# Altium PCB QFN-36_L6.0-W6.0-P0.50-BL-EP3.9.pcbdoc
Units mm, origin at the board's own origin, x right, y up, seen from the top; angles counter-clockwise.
Board outline 19.5 x 19.8 mm, 2 copper layers (Top Layer, Bottom Layer), stack 0 mm thick; 1 components, 0 nets, 37 pads, 0 vias.
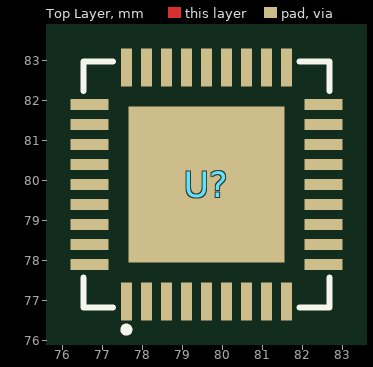
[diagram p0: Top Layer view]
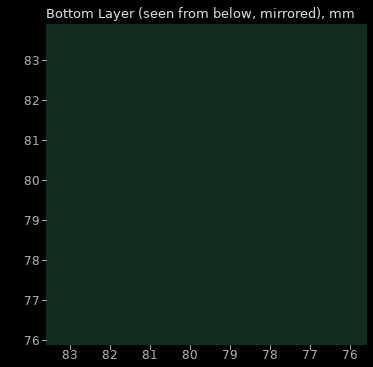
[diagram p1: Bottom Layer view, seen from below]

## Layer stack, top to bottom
Top Layer: signal copper (thickness not stored)
Bottom Layer: signal copper (thickness not stored)

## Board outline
89.35,69.85 69.85,69.85 69.85,89.655 89.35,89.655

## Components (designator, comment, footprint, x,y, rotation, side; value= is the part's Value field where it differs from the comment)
U? "" QFN-36_L6.0-W6.0-P0.50-BL-EP3.9 79.6,79.905 r0 top

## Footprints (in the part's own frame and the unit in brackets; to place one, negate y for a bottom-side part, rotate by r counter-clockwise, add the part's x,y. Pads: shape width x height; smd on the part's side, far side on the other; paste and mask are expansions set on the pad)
QFN-36_L6.0-W6.0-P0.50-BL-EP3.9 [mm]
  rect 0.28x0.95 smd paste-100 mask+0.051: 1(-2,-2.925) 2(-1.5,-2.925) 3(-1,-2.925) 4(-0.5,-2.925) 5(0,-2.925) 6(0.5,-2.925) 7(1,-2.925) 8(1.5,-2.925) 9(2,-2.925) 19(2,2.925) 20(1.5,2.925) 21(1,2.925) 22(0.5,2.925) 23(0,2.925) 24(-0.5,2.925) 25(-1,2.925) 26(-1.5,2.925) 27(-2,2.925)
  rect 0.95x0.28 smd paste-100 mask+0.051: 10(2.925,-2) 11(2.925,-1.5) 12(2.925,-1) 13(2.925,-0.5) 14(2.925,0) 15(2.925,0.5) 16(2.925,1) 17(2.925,1.5) 18(2.925,2) 28(-2.925,2) 29(-2.925,1.5) 30(-2.925,1) 31(-2.925,0.5) 32(-2.925,0) 33(-2.925,-0.5) 34(-2.925,-1) 35(-2.925,-1.5) 36(-2.925,-2)
  rect 3.9x3.9 smd paste-100 mask+0.051: 37(0,0)
  silkscreen extent -3.08,-3.7 3.08,3.08

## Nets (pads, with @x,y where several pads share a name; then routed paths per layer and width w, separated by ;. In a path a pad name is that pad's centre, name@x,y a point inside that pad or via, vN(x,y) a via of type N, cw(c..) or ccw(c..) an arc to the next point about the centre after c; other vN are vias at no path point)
pads on no net: U?.1 U?.2 U?.3 U?.4 U?.5 U?.6 U?.7 U?.8 U?.9 U?.10 U?.11 U?.12 U?.13 U?.14 U?.15 U?.16 U?.17 U?.18 U?.19 U?.20 U?.21 U?.22 U?.23 U?.24 U?.25 U?.26 U?.27 U?.28 U?.29 U?.30 U?.31 U?.32 U?.33 U?.34 U?.35 U?.36 U?.37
